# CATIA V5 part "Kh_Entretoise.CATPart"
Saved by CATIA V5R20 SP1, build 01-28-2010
Part number: Entretoise
Bounding box of the stored display mesh (mm): x 0 to 34, y -10.5 to 10.5, z -10.5 to 10.5
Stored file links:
  G:\Khaled_CFAO_2011\SIL\SIL_GR1\tmerino\Khaled\CAD_Thinkmotion\Kh_Entretoise.CATPart
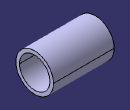
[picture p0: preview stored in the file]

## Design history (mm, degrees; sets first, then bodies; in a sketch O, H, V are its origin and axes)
Body1 (main body)
  Sketch1 on yz-plane, origin (0, 0, 0), H (0, 1, 0), V (0, 0, 1)
    circle A1 centre (0, 0) radius 8.5
    circle A2 centre (0, 0) radius 10.5
    radius A1 = 8.5
    radius A2 = 10.5
  Pad1: profile Sketch1, direction (1, 0, 0), length 34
